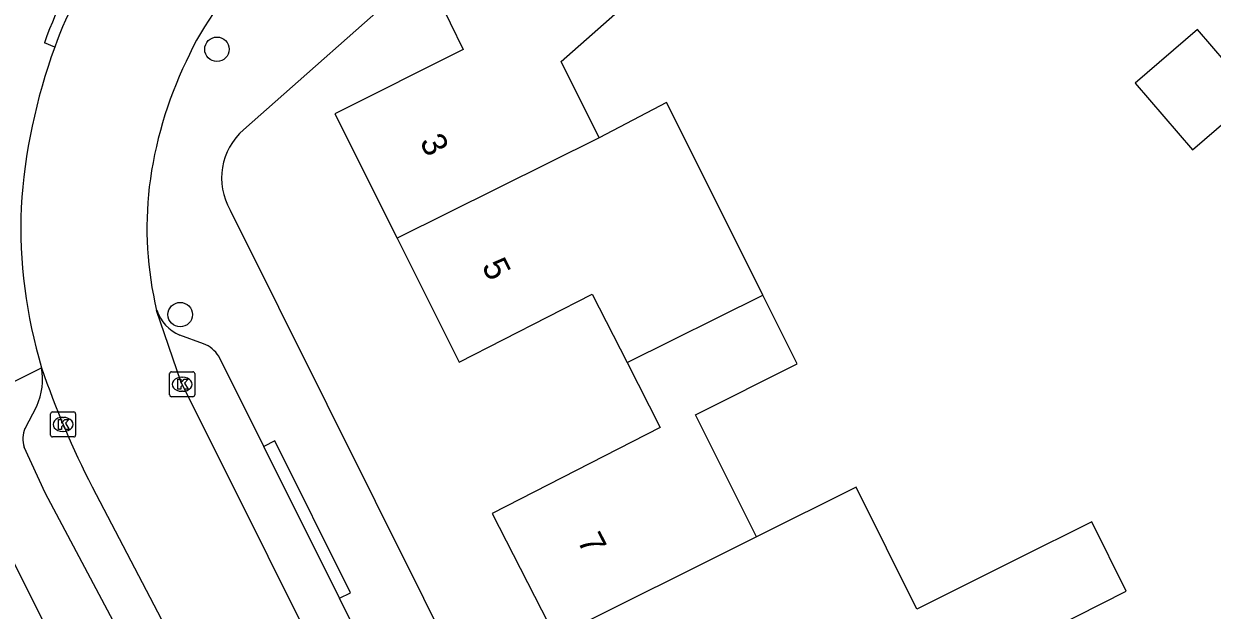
# Model space of a CAD drawing. Extents: x 157321 to 158827, y 386650 to 388532.
# Drawn here: x 157520.92 to 157568.44, y 387702.88 to 387726.32 of the extents above; entities that cross this region are included whole.
import ezdxf

# ---------------------------------------------------------------- set-up
doc = ezdxf.new("R2010")
doc.units = 0
for name, color, linetype in [('IMGEO_Boom', 7, 'Continuous'), ('IMGEO_Kolk', 7, 'Continuous'), ('IMGEO_Pand', 7, 'Continuous'), ('IMGEO_Pand_nummerreeks', 7, 'Continuous'), ('IMGEO_Rijbaan_lokaal_open', 7, 'Continuous'), ('IMGEO_Voetpad_open', 7, 'Continuous')]:
    doc.layers.add(name, color=color, linetype=linetype)

msp = doc.modelspace()

# ---------------------------------------------------------------- linework, layer by layer
at = {"layer": 'IMGEO_Boom'}
for centre in [(157528.644, 387725.295), (157527.175, 387714.691)]:
    msp.add_circle(centre, 0.489, dxfattribs=at)
at = {"layer": 'IMGEO_Kolk'}
for p, q in [((157526.754, 387711.48), (157526.754, 387712.332)), ((157526.829, 387712.406), (157527.681, 387712.406)), ((157527.242, 387712.186), (157527.267, 387712.186)), ((157527.755, 387712.332), (157527.755, 387711.48)), ((157527.265, 387711.626), (157527.24, 387711.626)), ((157527.681, 387711.406), (157526.829, 387711.406)), ((157521.991, 387709.877), (157521.991, 387710.729)), ((157522.066, 387710.803), (157522.918, 387710.803)), ((157522.992, 387710.729), (157522.992, 387709.877)), ((157522.479, 387710.583), (157522.504, 387710.583)), ((157522.918, 387709.803), (157522.066, 387709.803)), ((157522.502, 387710.023), (157522.477, 387710.023))]:
    msp.add_line(p, q, dxfattribs=at)
for points in [[(157526.754, 387711.48), (157526.754, 387712.332)], [(157526.829, 387712.406), (157527.681, 387712.406)], [(157527.075, 387712.106), (157527.198, 387712.106), (157527.198, 387711.955), (157527.328, 387712.106), (157527.492, 387712.106), (157527.346, 387711.955), (157527.499, 387711.706), (157527.347, 387711.706), (157527.262, 387711.87), (157527.198, 387711.803), (157527.198, 387711.706), (157527.075, 387711.706), (157527.075, 387712.106)], [(157527.755, 387712.332), (157527.755, 387711.48)], [(157527.681, 387711.406), (157526.829, 387711.406)], [(157521.991, 387709.877), (157521.991, 387710.729)], [(157522.066, 387710.803), (157522.918, 387710.803)], [(157522.992, 387710.729), (157522.992, 387709.877)], [(157522.312, 387710.503), (157522.435, 387710.503), (157522.435, 387710.352), (157522.565, 387710.503), (157522.729, 387710.503), (157522.583, 387710.352), (157522.736, 387710.103), (157522.584, 387710.103), (157522.499, 387710.267), (157522.435, 387710.2), (157522.435, 387710.103), (157522.312, 387710.103), (157522.312, 387710.503)], [(157522.918, 387709.803), (157522.066, 387709.803)]]:
    msp.add_lwpolyline(points, dxfattribs=at)
for centre, start, end in [((157526.831, 387712.33), 91.552, 178.448), ((157526.831, 387712.33), 91.552, 178.448), ((157527.679, 387712.33), 1.552, 88.448), ((157527.679, 387712.33), 1.552, 88.448), ((157526.831, 387711.482), 181.552, 268.448), ((157526.831, 387711.482), 181.552, 268.448), ((157527.679, 387711.482), 271.552, 358.448), ((157527.679, 387711.482), 271.552, 358.448), ((157522.068, 387710.727), 91.552, 178.448), ((157522.068, 387710.727), 91.552, 178.448), ((157522.916, 387710.727), 1.552, 88.448), ((157522.916, 387710.727), 1.552, 88.448), ((157522.068, 387709.879), 181.552, 268.448), ((157522.068, 387709.879), 181.552, 268.448), ((157522.916, 387709.879), 271.552, 358.448), ((157522.916, 387709.879), 271.552, 358.448)]:
    msp.add_arc(centre, 0.0765, start, end, dxfattribs=at)
for centre, major_axis, ratio, start_param, end_param in [((157527.241, 387711.906), (-0.387, 0.002), 0.722429, 4.712389, 7.853982), ((157527.266, 387711.906), (-0.39, 0.002), 0.717154, 1.570796, 4.712389), ((157522.478, 387710.303), (-0.387, 0.002), 0.722429, 4.712389, 7.853982), ((157522.503, 387710.303), (-0.39, 0.002), 0.717154, 1.570796, 4.712389)]:
    msp.add_ellipse(centre, major_axis=major_axis, ratio=ratio, start_param=start_param, end_param=end_param, dxfattribs=at)
at = {"layer": 'IMGEO_Pand'}
for points in [[(157543.926, 387721.761), (157542.402, 387724.809), (157547.031, 387728.898), (157543.554, 387732.833), (157537.443, 387727.432), (157538.493, 387725.281), (157533.364, 387722.716), (157535.845, 387717.747)], [(157565.353, 387723.943), (157567.644, 387721.273), (157570.148, 387723.422), (157567.856, 387726.092), (157565.353, 387723.943)], [(157550.469, 387715.475), (157549.078, 387718.258), (157546.617, 387723.175), (157543.926, 387721.761)], [(157543.926, 387721.761), (157535.845, 387717.747)], [(157535.845, 387717.747), (157538.323, 387712.785), (157543.643, 387715.508), (157545.041, 387712.778)], [(157545.041, 387712.778), (157550.469, 387715.475)], [(157550.218, 387705.806), (157547.777, 387710.69), (157551.844, 387712.723), (157551.313, 387713.786), (157550.469, 387715.475)], [(157545.041, 387712.778), (157546.368, 387710.185), (157539.647, 387706.744), (157542.177, 387701.802)], [(157562.02, 387702.131), (157565, 387703.642), (157563.62, 387706.405), (157560.631, 387704.912), (157556.633, 387702.915), (157554.205, 387707.791), (157550.218, 387705.806)], [(157550.218, 387705.806), (157542.177, 387701.802)]]:
    msp.add_lwpolyline(points, dxfattribs=at)
at = {"layer": 'IMGEO_Rijbaan_lokaal_open'}
for points in [[(157560.191, 387645.701), (157548.136, 387670.075), (157527.197, 387712.019), (157526.234, 387714.862)], [(157523.655, 387707.807), (157527.814, 387699.851)]]:
    msp.add_lwpolyline(points, dxfattribs=at)
for centre, radius, start, end in [((157539.658, 387719.046), 18.609, 131.7715, 160.098), ((157538.069, 387720.093), 11.65, 131.3997, 156.1371), ((157543.772, 387717.489), 23.008, 159.9387, 176.2984), ((157541.762, 387717.866), 15.939, 154.1874, 173.0446), ((157540.034, 387718.157), 14.188, 173.3674, 193.4295), ((157540.815, 387718.286), 20.015, 178.0297, 196.5967), ((157555.332, 387724.06), 35.603, 198.8302, 207.1626)]:
    msp.add_arc(centre, radius, start, end, dxfattribs=at)
at = {"layer": 'IMGEO_Voetpad_open'}
for points in [[(157572.416, 387759.957), (157551.146, 387741.084), (157548.792, 387738.997), (157536.727, 387728.304), (157529.707, 387722.081)], [(157522.16, 387725.381), (157521.746, 387725.558)], [(157529.176, 387718.871), (157552.382, 387672.317), (157551.863, 387672.031), (157564.366, 387646.663)], [(157528.106, 387713.526), (157527.154, 387713.874)], [(157530.515, 387709.42), (157528.716, 387713.026)], [(157517.619, 387710.56), (157521.634, 387712.569)], [(157520.97, 387710.144), (157521.442, 387711.038)], [(157517.619, 387710.56), (157526.243, 387693.326)], [(157525.063, 387701.376), (157521.775, 387707.568), (157520.935, 387709.397)], [(157533.54, 387703.354), (157533.987, 387703.577), (157530.962, 387709.643), (157530.515, 387709.42)], [(157533.54, 387703.354), (157530.515, 387709.42)], [(157538.324, 387693.762), (157533.54, 387703.354)]]:
    msp.add_lwpolyline(points, dxfattribs=at)
for centre, radius, start, end in [((157539.311, 387719.216), 18.675, 131.2827, 160.1491), ((157531.388, 387720.154), 2.557, 131.0953, 210.119), ((157527.827, 387715.423), 1.688, 199.3939, 246.5239), ((157527.669, 387712.371), 1.235, 32.0367, 69.2823), ((157519.048, 387712.116), 2.625, 335.7634, 9.9405), ((157521.906, 387709.726), 1.026, 155.9365, 198.6984)]:
    msp.add_arc(centre, radius, start, end, dxfattribs=at)

# ---------------------------------------------------------------- texts
at = {"layer": 'IMGEO_Pand_nummerreeks'}
for s, rotation, p in [('3', 296.5335, (157536.735, 387721.606)), ('5', 296.5335, (157539.215, 387716.64)), ('7', 297.1105, (157543.033, 387705.66))]:
    msp.add_text(s, height=1, rotation=rotation, dxfattribs=at).set_placement(p)

doc.saveas('drawing.dxf')
